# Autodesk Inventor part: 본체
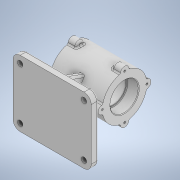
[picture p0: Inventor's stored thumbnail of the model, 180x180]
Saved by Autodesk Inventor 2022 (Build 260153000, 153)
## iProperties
Created: 2023-05
Part Number: 본체
Material: 일반
Document SubType Name: Modeling
Designer: Admin
Density: 1 g/cm^3
Appearance: 기본값
Author: Admin
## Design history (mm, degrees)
sketch "스케치1"
  geometry: L1 (-91, 0)-(91, 0) reference; L2 (0, -77)-(0, 77) reference; L3 (65, -55)-(-65, -55); L4 (-65, -55)-(-65, 55); L5 (-65, 55)-(65, 55); L6 (65, 55)-(65, -55); L7 (65, -55)-(-65, 55); L8 (-65, -55)-(65, 55); 1 further point
  constraints: 12 end point, 2 midpoint, 2 parallel, 1 horizontal, 1 perpendicular
  dimensions: "d0" = 130 distance of L4.end L5.end; "d1" = 110 distance of L5.end L3.start
extrude "돌출1" new body sketch "스케치1" distance "d2" = 12; taper "d3" = 0 deg
fillet "모깎기1" dims "d8" = 12
sketch "스케치3"
  geometry: L1 (93.982, 0)-(-91.497, 0) reference; L2 (0, -77.497)-(0, 79.982) reference; C1 r 4.5 at (53, 43); C2 r 4.5 at (53, -43); C3 r 4.5 at (-53, 43); C4 r 4.5 at (-53, -43); A1 r 12 centre (53, 43) between (65, 43) and (53, 55) reference; 1 further point
  constraints: 4 centre point, 3 symmetric about line, 1 coincident, 3 other
  dimensions: "d9" = 9 diameter of C1
extrude "돌출3" cut sketch "스케치3" stored distance "d10" = 87; taper "d11" = 0 deg
node "작업 평면1"
sketch "스케치5"
  geometry: L1 (0, -2.4)-(0, 14.4) reference; L2 (-77, 0)-(77, 0) reference; L3 (-43, 12)-(43, 12) reference; C1 r 37 at (0, -70); 1 further point
  constraints: 1 centre point, 1 point on line
  dimensions: "d14" = 82 distance from line of L3 C1.centre; "d15" = 74 diameter of C1
extrude "돌출4" join sketch "스케치5" stored distance "d16" = 87; taper "d17" = 0 deg
sketch "스케치6"
  geometry: L1 (0, -77)-(0, 77) reference; L2 (0, 41)-(10, 41); L3 (10, 41)-(10, -41); L4 (10, -41)-(0, -41); L5 (0, -41)-(0, 41); L6 (0, 41)-(10, -41); L7 (10, 41)-(0, -41); L8 (-65, -43)-(-65, 43) reference; L9 (-15, 5)-(25, 5); L10 (25, 5)-(25, -5); L11 (25, -5)-(-15, -5); L12 (-15, -5)-(-15, 5); L13 (-15, 5)-(25, -5); L14 (25, 5)-(-15, -5); L15 (91, 0)-(-91, 0) reference; L16 (53, -55)-(-53, -55) reference; 6 further points
  constraints: 24 end point, 4 midpoint, 4 parallel, 2 horizontal, 2 perpendicular, 1 point on line
  dimensions: "d18" = 70 distance from line of L8 point (5, 0); "d19" = 10 distance of L2.start L2.end; "d20" = 10 distance of L9.end L10.end; "d21" = 40 distance of L10.end L11.end; "d22" = 14 distance between parallel lines of L16 L4
extrude "돌출5" join sketch "스케치6" distance "d23" = 82; taper "d24" = 0 deg
feature "면 기울기1" dims angle "d25" = 20 deg
feature "면 기울기2" dims angle "d26" = 20 deg
sketch "스케치7"
  geometry: L1 (68.733, 0)-(-107.122, 0) reference; C1 r 7 at (37, 0); C2 r 7 at (0, 37); C3 r 7 at (-37, 0); C4 r 7 at (0, -37); 10 further points
  constraints: 4 centre point, 1 point on line, 11 other
  dimensions: "d27" = 14 diameter of C1; "d30" = 360 deg dimension on point (0, 0) C1.centre (derived)
extrude "돌출6" join sketch "스케치7" distance "d32" = 14; taper "d33" = 0 deg
sketch "스케치8"
  geometry: L1 (-69.2, 0)-(107.2, 0) reference; C1 r 7 at (-37, 0); C2 r 7 at (0, -37); C3 r 7 at (37, 0); C4 r 7 at (0, 37); A1 r 7 centre (-37, 0) between (-36.338, 6.969) and (-36.338, -6.969) reference; A2 r 37 centre (0, 0) between (-36.338, -6.969) and (-36.338, 6.969) reference; 3 further points
  constraints: 4 centre point, 1 coincident, 9 other
  dimensions: "d34" = 14 diameter of C1; "d37" = 360 deg dimension on A2.centre C1.centre (derived)
extrude "돌출7" join sketch "스케치8" distance "d39" = 14; taper "d40" = 0 deg
sketch "스케치9"
  geometry: A1 r 7 centre (107, 0) between (106.338, -6.969) and (106.338, 6.969) reference; A2 r 37 centre (70, 0) between (106.338, 6.969) and (76.969, 36.338) reference; A3 r 37 centre (70, 0) between (63.031, 36.338) and (33.662, 6.969) reference; A4 r 7 centre (33, 0) between (33.662, 6.969) and (33.662, -6.969) reference; A5 r 37 centre (70, 0) between (33.662, -6.969) and (63.031, -36.338) reference; A6 r 7 centre (70, -37) between (63.031, -36.338) and (76.969, -36.338) reference; A7 r 37 centre (70, 0) between (76.969, -36.338) and (106.338, -6.969) reference; A8 r 7 centre (107, 0) between (106.338, -6.969) and (106.338, 6.969) reference; A9 r 37 centre (70, 0) between (106.338, 6.969) and (76.969, 36.338) reference; A10 r 7 centre (70, 37) between (76.969, 36.338) and (63.031, 36.338) reference; A11 r 7 centre (70, -37) between (63.031, -36.338) and (76.969, -36.338) reference; 5 further points
  constraints: 4 coincident
hole "구멍1" sketch "스케치9" at (107, 0), (70, 37), (33, 0), (70, -37) diameter "d45" = 3.242; stored, may be unused: countersink angle "d49" = 82 deg, drill point angle "d51" = 118 deg; dims "d46" = 8, "d47" = 3.023, "d48" = 2, "d50" = 10
sketch "스케치10"
  geometry: C1 r 1.621 at (-107, 0) reference; C2 r 1.621 at (-33, 0) reference; A1 r 37 centre (-70, 0) between (-76.969, 36.338) and (-106.338, 6.969) reference; A2 r 37 centre (-70, 0) between (-33.662, 6.969) and (-63.031, 36.338) reference; A3 r 7 centre (-70, 37) between (-63.031, 36.338) and (-76.969, 36.338) reference; A4 r 37 centre (-70, 0) between (-76.969, 36.338) and (-106.338, 6.969) reference; A5 r 7 centre (-107, 0) between (-106.338, 6.969) and (-106.338, -6.969) reference; A6 r 37 centre (-70, 0) between (-106.338, -6.969) and (-76.969, -36.338) reference; A7 r 7 centre (-70, -37) between (-76.969, -36.338) and (-63.031, -36.338) reference; A8 r 37 centre (-70, 0) between (-63.031, -36.338) and (-33.662, -6.969) reference; A9 r 7 centre (-33, 0) between (-33.662, -6.969) and (-33.662, 6.969) reference; 5 further points
  constraints: 4 coincident
hole "구멍2" sketch "스케치10" at (-70, 37), (-107, 0), (-70, -37), (-33, 0) diameter "d52" = 3.242; stored, may be unused: countersink angle "d56" = 90 deg, drill point angle "d58" = 118 deg; dims "d53" = 8, "d54" = 4, "d55" = 2, "d57" = 10
fillet "모깎기6" dims "d59" = 3
sketch "스케치11"
  geometry: L1 (-139.2, 0)-(37.2, 0) reference; C1 r 23.5 at (-70, 0); A1 r 37 centre (-70, 0) between (-33.662, 6.969) and (-63.031, 36.338) reference; 1 further point
  constraints: 1 centre point, 1 concentric, 1 point on line
  dimensions: "d60" = 47 diameter of C1
extrude "돌출8" cut sketch "스케치11" distance "d61" = 19; taper "d62" = 0 deg
sketch "스케치12"
  geometry: C1 r 21 at (0, 0); A1 r 37 centre (0, 0) between (36.338, 6.969) and (6.969, 36.338) reference; 1 further point
  constraints: 1 centre point, 1 concentric
  dimensions: "d63" = 42 diameter of C1
extrude "돌출9" cut sketch "스케치12" distance "d64" = 49; taper "d65" = 0 deg
sketch "스케치13"
  geometry: C1 r 23.5 at (70, 0); A1 r 37 centre (70, 0) between (106.338, 6.969) and (76.969, 36.338) reference; 1 further point
  constraints: 1 centre point, 1 coincident
  dimensions: "d66" = 47 diameter of C1
extrude "돌출10" cut sketch "스케치13" distance "d67" = 19; taper "d68" = 0 deg
chamfer "모따기1" distance "d69" = 1; stored, may be unused: second distance "d70" = 2, angle "d71" = 45 deg
sketch "스케치14"
  geometry: L1 (0, 41)-(10, 41) reference; L2 (5, 41)-(5, -41); L3 (10, -41)-(0, -41) reference; 2 further points
  constraints: 2 end point, 2 midpoint, 1 horizontal alignment, 1 other
  dimensions: "d73" = 58 distance from line of L2 point (-53, 0)
feature "엠보싱1" sketch "스케치14" dims "d74" = 0.5, "d75" = 0
fillet "모깎기7" dims "d76" = 3
fillet "모깎기8" dims "d77" = 3
fillet "모깎기9" dims "d78" = 1
fillet "모깎기10" dims "d79" = 3
fillet "모깎기11" dims "d80" = 3
fillet "모깎기12" dims "d81" = 3
fillet "모깎기13" dims "d82" = 3
node "솔리드1"
node "투영된 루프1"
node "투영된 루프2"
feature "A9D066F2-1C7D-4E18-AEED-F7BC21143FA4" dims "d45" = 3.242, "d46" = 8, "d47" = 3.023, "d48" = 2, "d49" = 82 deg, "d50" = 10, "d51" = 118 deg
other parameters: "d13" = -5
